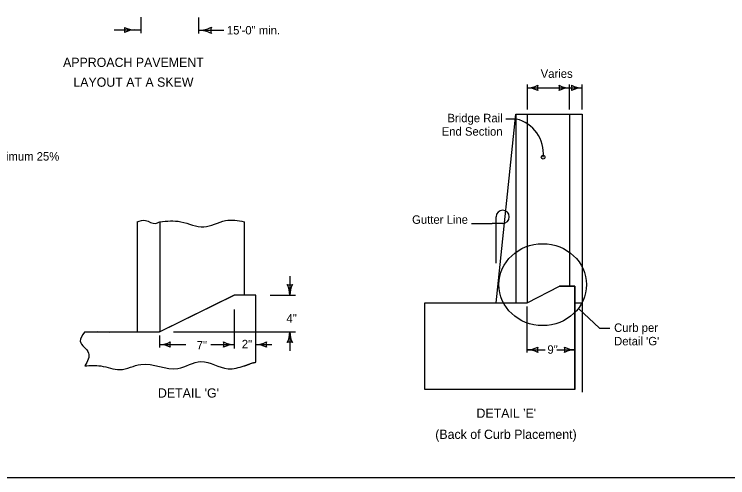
# Model space of a CAD drawing. Extents: x -2134934 to -2124557, y -2139046 to -2134021.
# Drawn here: x -2126647 to -2125295, y -2139046 to -2138168 of the extents above; entities that cross this region are included whole.
import ezdxf

# ---------------------------------------------------------------- set-up
doc = ezdxf.new("R2010")
doc.units = 0
for name, color, linetype in [('BridgeSuperStructureExisting', 7, 'Continuous'), ('dsnAlignmentStation', 7, 'Continuous'), ('dsnCellElements', 7, 'Continuous'), ('dsnStdLabel', 7, 'Continuous'), ('TC_Barrier', 7, 'Continuous')]:
    doc.layers.add(name, color=color, linetype=linetype)

msp = doc.modelspace()

# ---------------------------------------------------------------- linework, layer by layer
at = {"layer": 'BridgeSuperStructureExisting'}
for p, q in [((-2126406.9, -2138173.5), (-2126406.9, -2138203.7)), ((-2126297.8, -2138174.2), (-2126297.8, -2138204.4)), ((-2126457.8, -2138197.5), (-2126406.9, -2138197.5)), ((-2126297.8, -2138198.2), (-2126249.5, -2138198.2)), ((-2125675, -2138307.4), (-2125645.9, -2138307.4)), ((-2125674.7, -2138348), (-2125674.7, -2138300.7)), ((-2125674.7, -2138307.4), (-2125594.7, -2138307.4)), ((-2125599.1, -2138307.4), (-2125570.8, -2138307.4)), ((-2125594.7, -2138348), (-2125594.7, -2138300.7)), ((-2125570.8, -2138348), (-2125570.8, -2138300.7)), ((-2125733.9, -2138714.7), (-2125696.3, -2138357.1)), ((-2125696.3, -2138357.1), (-2125595, -2138357.1)), ((-2125696.3, -2138357.1), (-2125696.3, -2138714.7)), ((-2125675, -2138357.1), (-2125675, -2138714.7)), ((-2125595, -2138357.1), (-2125595, -2138683.1)), ((-2125595, -2138357.1), (-2125570.8, -2138357.1)), ((-2125570.8, -2138357.1), (-2125570.8, -2138883.5)), ((-2125696, -2138366.3), (-2125715.5, -2138366.3)), ((-2126413.9, -2138560.8), (-2126413.9, -2138769.8)), ((-2126371.2, -2138560.8), (-2126371.2, -2138769.8)), ((-2126211.2, -2138560.8), (-2126211.2, -2138699.9)), ((-2125780.3, -2138564.1), (-2125741.4, -2138564.1)), ((-2125733.9, -2138639.4), (-2125733.9, -2138571.6)), ((-2126211.2, -2138643.4), (-2126211.2, -2138699.9)), ((-2125595, -2138651.5), (-2125595, -2138683.1)), ((-2126124.7, -2138664.2), (-2126124.7, -2138699.9)), ((-2125584.7, -2138683.1), (-2125613.6, -2138683.1)), ((-2125613.6, -2138683.1), (-2125584.7, -2138683.1)), ((-2125584.7, -2138878.9), (-2125584.7, -2138683.1)), ((-2125584.7, -2138683.1), (-2125584.7, -2138878.9)), ((-2126189.3, -2138699.9), (-2126230, -2138699.9)), ((-2126189.3, -2138827.1), (-2126189.3, -2138699.9)), ((-2126161.8, -2138699.9), (-2126113.9, -2138699.9)), ((-2126230.1, -2138727.2), (-2126230.1, -2138801.1)), ((-2125675, -2138808.6), (-2125675, -2138721.2)), ((-2125584.7, -2138714.7), (-2125570.8, -2138714.7)), ((-2125578, -2138725.1), (-2125538, -2138762.7)), ((-2125538, -2138762.7), (-2125518.2, -2138762.7)), ((-2126489, -2138769.8), (-2126513.4, -2138769.9)), ((-2126372.4, -2138769.8), (-2126513.4, -2138769.9)), ((-2126513.2, -2138769.8), (-2126467.2, -2138769.9)), ((-2126467.2, -2138769.9), (-2126489, -2138769.8)), ((-2126371.3, -2138769.8), (-2126467.2, -2138769.9)), ((-2126467.2, -2138769.9), (-2126371.3, -2138769.8)), ((-2126371.2, -2138769.8), (-2126372.4, -2138769.8)), ((-2126371.3, -2138776.2), (-2126371.3, -2138799.1)), ((-2126345.4, -2138769.8), (-2126113.9, -2138769.8)), ((-2126124.7, -2138769.8), (-2126124.7, -2138805.5)), ((-2126371.2, -2138793.7), (-2126321.8, -2138793.7)), ((-2126274.2, -2138793.7), (-2126230.1, -2138793.7)), ((-2126189.2, -2138793.7), (-2126158.8, -2138793.7)), ((-2125675, -2138803.4), (-2125641.3, -2138803.4)), ((-2125618.9, -2138803.4), (-2125584.3, -2138803.4))]:
    msp.add_line(p, q, dxfattribs=at)
for points in [[(-2125675, -2138714.7), (-2125613.6, -2138683.1)], [(-2125675, -2138714.7), (-2125613.6, -2138683.1)], [(-2126230, -2138699.9), (-2126371.2, -2138769.8), (-2126371.3, -2138769.8)], [(-2126371.3, -2138769.8), (-2126230, -2138699.9)], [(-2126189.3, -2138699.9), (-2126211.2, -2138699.9), (-2126230, -2138699.9)], [(-2126189.3, -2138827.1), (-2126189.3, -2138827.1), (-2126189.3, -2138699.9)], [(-2125584.7, -2138878.9), (-2125869.1, -2138878.9), (-2125869.1, -2138714.7), (-2125723, -2138714.7), (-2125675, -2138714.7)], [(-2125584.7, -2138878.9), (-2125869.1, -2138878.9), (-2125869.1, -2138714.7), (-2125723, -2138714.7), (-2125675, -2138714.7)]]:
    msp.add_lwpolyline(points, dxfattribs=at)
for centre, radius, start, end in [((-2126452.3, -2138197.5), 15.5, 342.2666, 17.7334), ((-2126418.7, -2138157.3), 40.2, 241.9275, 270), ((-2126418.7, -2138237.7), 40.2, 90, 118.0725), ((-2126297.8, -2138146), 52.2, 270, 298.0725), ((-2126297.8, -2138250.5), 52.2, 61.9275, 90), ((-2126254.1, -2138198.3), 20.2, 162.2666, 197.7334), ((-2125711.1, -2138431.2), 66.7, 353.5756, 76.8823)]:
    msp.add_arc(centre, radius, start, end, dxfattribs=at)
msp.add_ellipse((-2125645.7, -2138680.1), major_axis=(83, 0), ratio=0.93542, dxfattribs=at)
for points in [[(-2126413.9, -2138560.8), (-2126398.2, -2138558.3), (-2126379.1, -2138564.2), (-2126371.2, -2138560.8)], [(-2126371.2, -2138560.8), (-2126331.1, -2138560.8), (-2126287.4, -2138570.8), (-2126246.6, -2138558.6), (-2126211.2, -2138560.8)], [(-2126513.4, -2138769.9), (-2126521.7, -2138787.4), (-2126505.9, -2138809.6), (-2126513.2, -2138834.1)], [(-2126513.4, -2138769.9), (-2126521.7, -2138787.4), (-2126505.9, -2138809.6), (-2126513.2, -2138834.1)], [(-2126513.2, -2138834.1), (-2126482.6, -2138834.1), (-2126446.4, -2138841.1), (-2126406.8, -2138831.2), (-2126336.8, -2138838.8), (-2126293, -2138825.9), (-2126241.7, -2138839.4), (-2126211.2, -2138834.1)], [(-2126513.2, -2138834.1), (-2126482.6, -2138834.1), (-2126446.4, -2138841.1), (-2126406.8, -2138831.2), (-2126336.8, -2138838.8), (-2126293, -2138825.9), (-2126241.7, -2138839.4), (-2126211.2, -2138834.1)], [(-2126211.2, -2138834.1), (-2126197.1, -2138829), (-2126191.8, -2138827.5)]]:
    msp.add_spline(points, degree=3, dxfattribs=at)
msp.add_open_spline([(-2126211.2, -2138834.1), (-2126210.3, -2138833.8), (-2126209.4, -2138833.6), (-2126208.5, -2138833.2), (-2126207.5, -2138832.9), (-2126206.6, -2138832.6), (-2126205.7, -2138832.2), (-2126203.9, -2138831.5), (-2126202.1, -2138830.8), (-2126200.2, -2138830.1), (-2126198.4, -2138829.4), (-2126196.6, -2138828.8), (-2126194.7, -2138828.2), (-2126193.8, -2138827.9), (-2126192.9, -2138827.7), (-2126192, -2138827.5), (-2126191.5, -2138827.5), (-2126191.1, -2138827.4), (-2126190.6, -2138827.3), (-2126190.2, -2138827.2), (-2126189.7, -2138827.2), (-2126189.3, -2138827.1)], degree=3, dxfattribs=at)
at = {"layer": 'dsnAlignmentStation'}
msp.add_lwpolyline([(-2127734.4, -2137035.9), (-2124599.4, -2137035.9), (-2124599.4, -2139045.9), (-2127734.4, -2139045.9)], close=True, dxfattribs=at)
at = {"layer": 'dsnCellElements'}
for centre, radius, start, end in [((-2125675, -2138264.9), 42.5, 270, 298.0725), ((-2125675, -2138349.9), 42.5, 61.9275, 90), ((-2125639.3, -2138307.4), 16.4, 162.2666, 197.7334), ((-2125630.3, -2138307.4), 16.4, 342.2666, 17.7333), ((-2125594.7, -2138264.9), 42.5, 241.9275, 270), ((-2125594.7, -2138349.9), 42.5, 90, 118.0725), ((-2125606.4, -2138307.4), 16.4, 342.2666, 17.7333), ((-2125570.8, -2138264.9), 42.5, 241.9275, 270), ((-2125570.8, -2138349.9), 42.5, 90, 118.0725), ((-2126124.7, -2138664.2), 16.4, 252.2666, 287.7333), ((-2126167.2, -2138699.9), 42.5, 360, 28.0725), ((-2126082.2, -2138699.9), 42.5, 151.9275, 180), ((-2126167.2, -2138769.8), 42.5, 331.9275, 360), ((-2126082.2, -2138769.8), 42.5, 180, 208.0725), ((-2126371.2, -2138751.2), 42.5, 270, 298.0725), ((-2126371.2, -2138836.2), 42.5, 61.9275, 90), ((-2126335.6, -2138793.7), 16.4, 162.2666, 197.7334), ((-2126265.8, -2138793.7), 16.4, 342.2666, 17.7333), ((-2126230.1, -2138751.2), 42.5, 241.9275, 270), ((-2126230.1, -2138836.2), 42.5, 90, 118.0725), ((-2126189.2, -2138751.2), 42.5, 270, 298.0725), ((-2126189.2, -2138836.2), 42.5, 61.9275, 90), ((-2126153.6, -2138793.7), 16.4, 162.2666, 197.7334), ((-2126124.7, -2138805.4), 16.4, 72.2666, 107.7334), ((-2125675, -2138760.9), 42.5, 270, 298.0725), ((-2125675, -2138845.9), 42.5, 61.9275, 90), ((-2125639.3, -2138803.4), 16.4, 162.2666, 197.7334), ((-2125619.9, -2138803.4), 16.4, 342.2666, 17.7333), ((-2125584.3, -2138760.9), 42.5, 241.9275, 270), ((-2125584.3, -2138845.9), 42.5, 90, 118.0725)]:
    msp.add_arc(centre, radius, start, end, dxfattribs=at)
at = {"layer": 'TC_Barrier'}
for p, q in [((-2125733.9, -2138571.6), (-2125733.9, -2138551.6)), ((-2125721.4, -2138564.1), (-2125741.4, -2138564.1))]:
    msp.add_line(p, q, dxfattribs=at)
msp.add_circle((-2125644.9, -2138438.7), 3.54, dxfattribs=at)
msp.add_arc((-2125721.4, -2138551.6), 12.5, 270, 180, dxfattribs=at)

# ---------------------------------------------------------------- texts
at = {"layer": 'BridgeSuperStructureExisting'}
for s, height, p in [('APPROACH PAVEMENT', 17.5, (-2126554.3, -2138267.6)), ('Varies', 16, (-2125649.5, -2138288.2)), ('LAYOUT AT A SKEW', 17.5, (-2126534.8, -2138305.1)), ('Bridge Rail ', 16, (-2125826.1, -2138372.4)), ('End Section', 16, (-2125837, -2138397.8)), ('Gutter Line', 16, (-2125893.1, -2138564.8)), ('4"', 16, (-2126131.1, -2138752)), ('Curb per', 16, (-2125510.4, -2138769.6)), ("Detail 'G'", 16, (-2125510.4, -2138795.1)), ('7"', 16, (-2126301.1, -2138802.8)), ('2"', 16, (-2126215.7, -2138800.7)), ('9"', 16, (-2125636.7, -2138811)), ("DETAIL 'G'", 17.5, (-2126374.5, -2138894.1)), ("DETAIL 'E'", 17.5, (-2125771.1, -2138932.4))]:
    msp.add_text(s, height=height, dxfattribs=at).set_placement(p)
at = {"layer": 'dsnStdLabel'}
for s, height, p in [('15\'-0" min.', 16, (-2126244, -2138206)), ('Closed Cell Backer Rod (minimum 25%', 16, (-2126937.2, -2138445)), ('(Back of Curb Placement)', 17.5, (-2125849.2, -2138972.4))]:
    msp.add_text(s, height=height, dxfattribs=at).set_placement(p)

doc.saveas('drawing.dxf')
